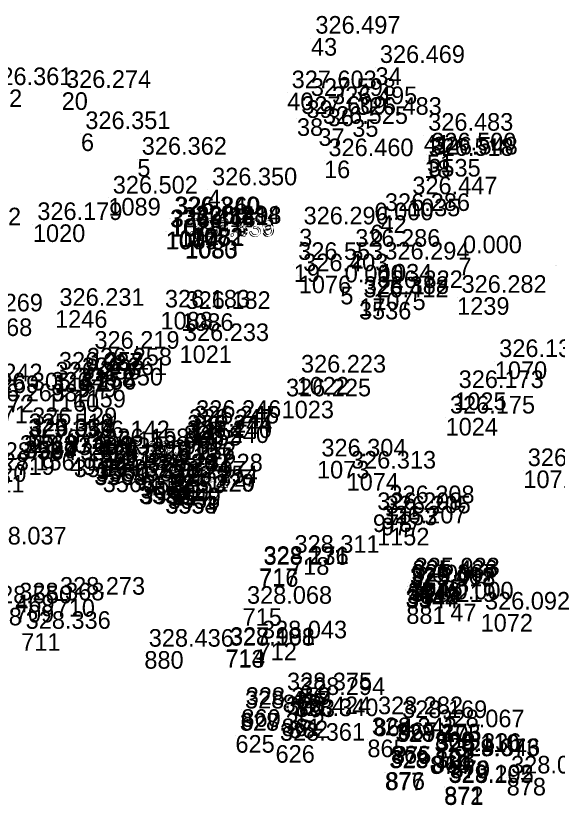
# Model space of a CAD drawing. Extents: x -829398 to -819400, y -1074439 to -1067977.
# Drawn here: x -823610.7 to -823573.8, y -1070251.6 to -1070197.8 of the extents above; entities that cross this region are included whole.
import ezdxf

# ---------------------------------------------------------------- set-up
doc = ezdxf.new("R2010")
doc.units = 0
doc.layers.add('Vrstva 60', color=7, linetype='Continuous')
doc.layers.add('Vrstva 61', color=7, linetype='Continuous')

msp = doc.modelspace()

# ---------------------------------------------------------------- linework, layer by layer
at = {"layer": 'Vrstva 60'}
for p, q in [((-823590.598, -1070199.294), (-823590.598, -1070199.294)), ((-823586.202, -1070201.291), (-823586.202, -1070201.291)), ((-823607.598, -1070202.992), (-823607.598, -1070202.992)), ((-823592.216, -1070203.012), (-823592.216, -1070203.012)), ((-823590.908, -1070203.54), (-823590.908, -1070203.54)), ((-823589.458, -1070204.102), (-823589.458, -1070204.102)), ((-823591.554, -1070204.765), (-823591.554, -1070204.765)), ((-823587.783, -1070204.827), (-823587.783, -1070204.827)), ((-823590.087, -1070205.446), (-823590.087, -1070205.446)), ((-823606.283, -1070205.799), (-823606.283, -1070205.799)), ((-823582.907, -1070205.912), (-823582.907, -1070205.912)), ((-823602.436, -1070207.547), (-823602.436, -1070207.547)), ((-823589.708, -1070207.648), (-823589.708, -1070207.648)), ((-823582.876, -1070207.626), (-823582.876, -1070207.626)), ((-823582.698, -1070207.252), (-823582.698, -1070207.252)), ((-823582.599, -1070207.539), (-823582.599, -1070207.539)), ((-823597.639, -1070209.635), (-823597.639, -1070209.635)), ((-823604.412, -1070210.197), (-823604.412, -1070210.197)), ((-823583.988, -1070210.246), (-823583.988, -1070210.246)), ((-823585.859, -1070211.384), (-823585.859, -1070211.384)), ((-823600.214, -1070211.606), (-823600.214, -1070211.606)), ((-823600.144, -1070211.632), (-823600.144, -1070211.632)), ((-823609.557, -1070212), (-823609.557, -1070212)), ((-823600.512, -1070212.501), (-823600.512, -1070212.501)), ((-823600.46, -1070212.486), (-823600.46, -1070212.486)), ((-823599.6, -1070212.333), (-823599.6, -1070212.333)), ((-823598.784, -1070212.226), (-823598.784, -1070212.226)), ((-823598.711, -1070212.264), (-823598.711, -1070212.264)), ((-823591.403, -1070212.298), (-823591.403, -1070212.298)), ((-823586.564, -1070212.02), (-823586.564, -1070212.02)), ((-823599.192, -1070213.133), (-823599.192, -1070213.133)), ((-823599.153, -1070213.092), (-823599.153, -1070213.092)), ((-823587.88, -1070213.824), (-823587.88, -1070213.824)), ((-823580.535, -1070214.267), (-823580.535, -1070214.267)), ((-823591.772, -1070214.721), (-823591.772, -1070214.721)), ((-823585.895, -1070214.697), (-823585.895, -1070214.697)), ((-823573.926, -1070214.791), (-823573.926, -1070214.791)), ((-823573.863, -1070214.779), (-823573.863, -1070214.779)), ((-823591.431, -1070215.494), (-823591.431, -1070215.494)), ((-823588.595, -1070216.253), (-823588.595, -1070216.253)), ((-823586.352, -1070216.64), (-823586.352, -1070216.64)), ((-823587.327, -1070217.278), (-823587.327, -1070217.278)), ((-823587.295, -1070217.043), (-823587.295, -1070217.043)), ((-823580.634, -1070216.965), (-823580.634, -1070216.965)), ((-823608.048, -1070217.853), (-823608.048, -1070217.853)), ((-823600.857, -1070217.967), (-823600.857, -1070217.967)), ((-823599.448, -1070218.063), (-823599.448, -1070218.063)), ((-823599.56, -1070220.253), (-823599.56, -1070220.253)), ((-823605.662, -1070220.777), (-823605.662, -1070220.777)), ((-823578.066, -1070221.343), (-823578.066, -1070221.343)), ((-823608.083, -1070222.205), (-823608.083, -1070222.205)), ((-823606.176, -1070221.92), (-823606.176, -1070221.92)), ((-823606.515, -1070222.577), (-823606.515, -1070222.577)), ((-823591.58, -1070222.404), (-823591.58, -1070222.404)), ((-823608.312, -1070222.876), (-823608.312, -1070222.876)), ((-823606.787, -1070223.284), (-823606.787, -1070223.284)), ((-823608.615, -1070223.568), (-823608.615, -1070223.568)), ((-823580.831, -1070223.457), (-823580.831, -1070223.457)), ((-823592.601, -1070224.025), (-823592.601, -1070224.025)), ((-823581.421, -1070225.196), (-823581.421, -1070225.196)), ((-823598.871, -1070225.877), (-823598.871, -1070225.877)), ((-823598.728, -1070225.493), (-823598.728, -1070225.493)), ((-823610.137, -1070226.4), (-823610.137, -1070226.4)), ((-823609.912, -1070225.983), (-823609.912, -1070225.983)), ((-823599.333, -1070226.498), (-823599.333, -1070226.498)), ((-823599.212, -1070226.092), (-823599.212, -1070226.092)), ((-823610.178, -1070226.77), (-823610.178, -1070226.77)), ((-823610.106, -1070226.739), (-823610.106, -1070226.739)), ((-823606.326, -1070226.884), (-823606.326, -1070226.884)), ((-823599.358, -1070226.867), (-823599.358, -1070226.867)), ((-823604.997, -1070227.424), (-823604.997, -1070227.424)), ((-823599.559, -1070227.205), (-823599.559, -1070227.205)), ((-823573.818, -1070227.288), (-823573.818, -1070227.288)), ((-823607.04, -1070227.894), (-823607.04, -1070227.894)), ((-823606.768, -1070228.03), (-823606.768, -1070228.03)), ((-823605.85, -1070227.601), (-823605.85, -1070227.601)), ((-823590.188, -1070228.125), (-823590.188, -1070228.125)), ((-823605.373, -1070228.542), (-823605.373, -1070228.542)), ((-823605.364, -1070228.58), (-823605.364, -1070228.58)), ((-823605.267, -1070228.34), (-823605.267, -1070228.34)), ((-823605.209, -1070228.17), (-823605.209, -1070228.17)), ((-823601.811, -1070228.316), (-823601.811, -1070228.316)), ((-823604.798, -1070229.057), (-823604.798, -1070229.057)), ((-823602.039, -1070229.133), (-823602.039, -1070229.133)), ((-823599.985, -1070229.138), (-823599.985, -1070229.138)), ((-823588.169, -1070228.952), (-823588.169, -1070228.952)), ((-823576.118, -1070228.78), (-823576.118, -1070228.78)), ((-823602.222, -1070229.491), (-823602.222, -1070229.491)), ((-823601.138, -1070229.626), (-823601.138, -1070229.626)), ((-823602.336, -1070229.84), (-823602.336, -1070229.84)), ((-823602.24, -1070229.885), (-823602.24, -1070229.885)), ((-823600.364, -1070230.195), (-823600.364, -1070230.195)), ((-823600.323, -1070229.946), (-823600.323, -1070229.946)), ((-823600.54, -1070230.517), (-823600.54, -1070230.517)), ((-823600.519, -1070230.524), (-823600.519, -1070230.524)), ((-823585.55, -1070231.31), (-823585.55, -1070231.31)), ((-823586.379, -1070231.776), (-823586.379, -1070231.776)), ((-823585.803, -1070232.003), (-823585.803, -1070232.003)), ((-823586.094, -1070232.691), (-823586.094, -1070232.691)), ((-823592.021, -1070234.692), (-823592.021, -1070234.692)), ((-823594.132, -1070235.51), (-823594.132, -1070235.51)), ((-823594.131, -1070235.449), (-823594.131, -1070235.449)), ((-823584.049, -1070236.669), (-823584.049, -1070236.669)), ((-823584, -1070236.707), (-823584, -1070236.707)), ((-823583.971, -1070236.399), (-823583.971, -1070236.399)), ((-823583.829, -1070236.235), (-823583.829, -1070236.235)), ((-823584.155, -1070236.872), (-823584.155, -1070236.872)), ((-823584.126, -1070236.979), (-823584.126, -1070236.979)), ((-823608.009, -1070237.55), (-823608.009, -1070237.55)), ((-823595.26, -1070238.17), (-823595.26, -1070238.17)), ((-823584.098, -1070238.039), (-823584.098, -1070238.039)), ((-823581.1, -1070237.871), (-823581.1, -1070237.871)), ((-823579.034, -1070238.565), (-823579.034, -1070238.565)), ((-823610.352, -1070239.878), (-823610.352, -1070239.878)), ((-823596.435, -1070241.025), (-823596.435, -1070241.025)), ((-823596.417, -1070240.971), (-823596.417, -1070240.971)), ((-823594.238, -1070240.527), (-823594.238, -1070240.527)), ((-823601.959, -1070241.097), (-823601.959, -1070241.097)), ((-823592.532, -1070244.07), (-823592.532, -1070244.07)), ((-823591.643, -1070244.389), (-823591.643, -1070244.389)), ((-823595.402, -1070245.31), (-823595.402, -1070245.31)), ((-823595.345, -1070245.061), (-823595.345, -1070245.061)), ((-823592.601, -1070245.696), (-823592.601, -1070245.696)), ((-823592.106, -1070245.834), (-823592.106, -1070245.834)), ((-823586.33, -1070245.7), (-823586.33, -1070245.7)), ((-823584.684, -1070245.96), (-823584.684, -1070245.96)), ((-823595.748, -1070246.824), (-823595.748, -1070246.824)), ((-823582.138, -1070246.589), (-823582.138, -1070246.589)), ((-823593.015, -1070247.51), (-823593.015, -1070247.51)), ((-823586.751, -1070247.131), (-823586.751, -1070247.131)), ((-823585.14, -1070247.555), (-823585.14, -1070247.555)), ((-823585.077, -1070247.589), (-823585.077, -1070247.589)), ((-823582.484, -1070248.273), (-823582.484, -1070248.273)), ((-823582.358, -1070248.203), (-823582.358, -1070248.203)), ((-823581.13, -1070248.57), (-823581.13, -1070248.57)), ((-823581.079, -1070248.552), (-823581.079, -1070248.552)), ((-823585.559, -1070249.383), (-823585.559, -1070249.383)), ((-823585.505, -1070249.351), (-823585.505, -1070249.351)), ((-823577.254, -1070249.74), (-823577.254, -1070249.74)), ((-823581.522, -1070250.339), (-823581.522, -1070250.339)), ((-823581.509, -1070250.389), (-823581.509, -1070250.389))]:
    msp.add_line(p, q, dxfattribs=at)

# ---------------------------------------------------------------- texts
for s, p in [('43', (-823590.598, -1070200.494)), ('34', (-823586.202, -1070202.491)), ('672', (-823612.966, -1070204.001)), ('20', (-823607.598, -1070204.192)), ('40', (-823592.216, -1070204.212)), ('39', (-823590.908, -1070204.74)), ('36', (-823589.458, -1070205.302)), ('38', (-823591.554, -1070205.965)), ('35', (-823587.783, -1070206.027)), ('37', (-823590.087, -1070206.646)), ('6', (-823606.283, -1070206.999)), ('41', (-823582.907, -1070207.112)), ('5', (-823602.436, -1070208.747)), ('16', (-823589.708, -1070208.848)), ('18', (-823582.876, -1070208.826)), ('51', (-823582.698, -1070208.452)), ('3535', (-823582.599, -1070208.739)), ('4', (-823597.639, -1070210.835)), ('1089', (-823604.412, -1070211.397)), ('1035', (-823583.988, -1070211.446)), ('42', (-823585.859, -1070212.584)), ('1020', (-823609.557, -1070213.2)), ('1078', (-823600.214, -1070212.806)), ('1085', (-823600.144, -1070212.832)), ('1079', (-823600.512, -1070213.701)), ('1084', (-823600.46, -1070213.686)), ('1077', (-823599.6, -1070213.533)), ('1082', (-823598.784, -1070213.426)), ('1081', (-823598.711, -1070213.464)), ('3', (-823591.403, -1070213.498)), ('6', (-823586.564, -1070213.22)), ('1080', (-823599.192, -1070214.333)), ('1083', (-823599.153, -1070214.292)), ('2', (-823587.88, -1070215.024)), ('7', (-823580.535, -1070215.467)), ('19', (-823591.772, -1070215.921)), ('1034', (-823585.895, -1070215.897)), ('1076', (-823591.431, -1070216.694)), ('5', (-823588.595, -1070217.453)), ('1075', (-823586.352, -1070217.84)), ('3536', (-823587.327, -1070218.478)), ('17', (-823587.295, -1070218.243)), ('1239', (-823580.634, -1070218.165)), ('1246', (-823608.048, -1070219.053)), ('1088', (-823600.857, -1070219.167)), ('1086', (-823599.448, -1070219.263)), ('1021', (-823599.56, -1070221.453)), ('1087', (-823605.662, -1070221.977)), ('1070', (-823578.066, -1070222.543)), ('1161', (-823608.083, -1070223.405)), ('1158', (-823606.176, -1070223.12)), ('979', (-823606.515, -1070223.777)), ('1022', (-823591.58, -1070223.604)), ('982', (-823608.312, -1070224.076)), ('1159', (-823606.787, -1070224.484)), ('3572', (-823613.056, -1070224.816)), ('1160', (-823608.615, -1070224.768)), ('1025', (-823580.831, -1070224.657)), ('3571', (-823613.474, -1070225.562)), ('1023', (-823592.601, -1070225.225)), ('1024', (-823581.421, -1070226.396)), ('3570', (-823609.912, -1070227.183)), ('1155', (-823598.871, -1070227.077)), ('1154', (-823598.728, -1070226.693)), ('3568', (-823610.137, -1070227.6)), ('981', (-823599.333, -1070227.698)), ('980', (-823599.212, -1070227.292)), ('3567', (-823610.178, -1070227.97)), ('3569', (-823610.106, -1070227.939)), ('3562', (-823606.326, -1070228.084)), ('1156', (-823599.358, -1070228.067)), ('1091', (-823605.85, -1070228.801)), ('3561', (-823604.997, -1070228.624)), ('1157', (-823599.559, -1070228.405)), ('719', (-823610.744, -1070229.079)), ('49', (-823607.04, -1070229.094)), ('3563', (-823606.768, -1070229.23)), ('1073', (-823590.188, -1070229.325)), ('720', (-823612.675, -1070229.56)), ('3564', (-823605.373, -1070229.742)), ('3565', (-823605.364, -1070229.78)), ('3559', (-823605.267, -1070229.54)), ('3560', (-823605.209, -1070229.37)), ('3551', (-823601.811, -1070229.516)), ('721', (-823612.809, -1070230.278)), ('3566', (-823604.798, -1070230.257)), ('3558', (-823602.039, -1070230.333)), ('3550', (-823599.985, -1070230.338)), ('1074', (-823588.169, -1070230.152)), ('1071', (-823576.118, -1070229.98)), ('3557', (-823602.222, -1070230.691)), ('1090', (-823601.138, -1070230.826)), ('3556', (-823602.336, -1070231.04)), ('3552', (-823602.24, -1070231.085)), ('3555', (-823600.364, -1070231.395)), ('3549', (-823600.323, -1070231.146)), ('3553', (-823600.54, -1070231.717)), ('3554', (-823600.519, -1070231.724)), ('1153', (-823585.55, -1070232.51)), ('978', (-823586.379, -1070232.976)), ('977', (-823585.803, -1070233.203)), ('1152', (-823586.094, -1070233.891)), ('718', (-823592.021, -1070235.892)), ('716', (-823594.132, -1070236.71)), ('717', (-823594.131, -1070236.649)), ('3548', (-823584.049, -1070237.869)), ('48', (-823584, -1070237.907)), ('3546', (-823583.971, -1070237.599)), ('3545', (-823583.829, -1070237.435)), ('3547', (-823584.155, -1070238.072)), ('3544', (-823584.126, -1070238.179)), ('710', (-823608.009, -1070238.75)), ('708', (-823612.988, -1070239.343)), ('709', (-823610.788, -1070239.138)), ('715', (-823595.26, -1070239.37)), ('881', (-823584.098, -1070239.239)), ('47', (-823581.1, -1070239.071)), ('1072', (-823579.034, -1070239.765)), ('711', (-823610.352, -1070241.078)), ('712', (-823594.238, -1070241.727)), ('713', (-823596.435, -1070242.225)), ('714', (-823596.417, -1070242.171)), ('880', (-823601.959, -1070242.297)), ('879', (-823592.532, -1070245.27)), ('863', (-823591.643, -1070245.589)), ('627', (-823595.402, -1070246.51)), ('860', (-823595.345, -1070246.261)), ('861', (-823592.601, -1070246.896)), ('862', (-823592.106, -1070247.034)), ('864', (-823586.33, -1070246.9)), ('867', (-823584.684, -1070247.16)), ('625', (-823595.748, -1070248.024)), ('868', (-823582.138, -1070247.789)), ('626', (-823593.015, -1070248.71)), ('865', (-823586.751, -1070248.331)), ('866', (-823585.14, -1070248.755)), ('875', (-823585.077, -1070248.789)), ('874', (-823582.484, -1070249.473)), ('869', (-823582.358, -1070249.403)), ('873', (-823581.13, -1070249.77)), ('870', (-823581.079, -1070249.752)), ('877', (-823585.559, -1070250.583)), ('876', (-823585.505, -1070250.551)), ('878', (-823577.254, -1070250.94)), ('872', (-823581.522, -1070251.539)), ('871', (-823581.509, -1070251.589))]:
    msp.add_text(s, height=1.2, dxfattribs=at).set_placement(p)
at = {"layer": 'Vrstva 61'}
for s, p in [('326.497', (-823590.298, -1070198.994)), ('326.469', (-823585.902, -1070200.991)), ('326.361', (-823612.666, -1070202.501)), ('326.274', (-823607.298, -1070202.692)), ('327.603', (-823591.916, -1070202.712)), ('327.598', (-823590.608, -1070203.24)), ('326.495', (-823589.158, -1070203.802)), ('327.609', (-823591.254, -1070204.465)), ('326.483', (-823587.483, -1070204.527)), ('326.351', (-823605.983, -1070205.499)), ('326.525', (-823589.787, -1070205.146)), ('326.483', (-823582.607, -1070205.612)), ('326.362', (-823602.136, -1070207.247)), ('326.500', (-823582.398, -1070206.952)), ('326.548', (-823582.299, -1070207.239)), ('326.460', (-823589.408, -1070207.348)), ('326.518', (-823582.576, -1070207.326)), ('326.350', (-823597.339, -1070209.335)), ('326.502', (-823604.112, -1070209.897)), ('326.447', (-823583.688, -1070209.946)), ('326.340', (-823599.914, -1070211.306)), ('326.860', (-823599.844, -1070211.332)), ('326.286', (-823585.559, -1070211.084)), ('326.382', (-823616.163, -1070212.064)), ('326.179', (-823609.257, -1070211.7)), ('326.821', (-823599.3, -1070212.033)), ('326.884', (-823598.484, -1070211.926)), ('326.498', (-823598.411, -1070211.964)), ('326.296', (-823591.103, -1070211.998)), ('0.000', (-823586.264, -1070211.72)), ('326.444', (-823600.212, -1070212.201)), ('326.815', (-823600.16, -1070212.186)), ('326.439', (-823598.892, -1070212.833)), ('326.836', (-823598.853, -1070212.792)), ('326.286', (-823587.58, -1070213.524)), ('0.000', (-823580.235, -1070213.967)), ('326.553', (-823591.472, -1070214.421)), ('326.294', (-823585.595, -1070214.397)), ('326.403', (-823591.131, -1070215.194)), ('0.000', (-823588.295, -1070215.953)), ('326.322', (-823586.052, -1070216.34)), ('326.388', (-823586.995, -1070216.743)), ('326.282', (-823580.334, -1070216.665)), ('326.412', (-823587.027, -1070216.978)), ('326.269', (-823614.676, -1070217.932)), ('326.231', (-823607.748, -1070217.553)), ('326.183', (-823600.557, -1070217.667)), ('326.182', (-823599.148, -1070217.763)), ('326.268', (-823615.404, -1070219.611)), ('326.233', (-823599.26, -1070219.953)), ('326.219', (-823605.362, -1070220.477)), ('326.137', (-823577.766, -1070221.043)), ('326.258', (-823605.876, -1070221.62)), ('326.258', (-823607.783, -1070221.905)), ('326.261', (-823606.215, -1070222.277)), ('326.223', (-823591.28, -1070222.104)), ('326.242', (-823614.701, -1070222.7)), ('326.256', (-823608.012, -1070222.576)), ('326.305', (-823612.756, -1070223.316)), ('326.256', (-823608.315, -1070223.268)), ('326.250', (-823606.487, -1070222.984)), ('326.173', (-823580.531, -1070223.157)), ('326.269', (-823614.933, -1070223.499)), ('326.225', (-823592.301, -1070223.725)), ('326.263', (-823613.174, -1070224.062)), ('326.175', (-823581.121, -1070224.896)), ('326.245', (-823598.571, -1070225.577)), ('326.246', (-823598.428, -1070225.193)), ('325.519', (-823609.837, -1070226.1)), ('326.129', (-823609.612, -1070225.683)), ('326.247', (-823598.912, -1070225.792)), ('325.356', (-823609.878, -1070226.47)), ('326.034', (-823609.806, -1070226.439)), ('326.142', (-823606.026, -1070226.584)), ('326.240', (-823599.058, -1070226.567)), ('326.244', (-823599.033, -1070226.198)), ('326.158', (-823604.697, -1070227.124)), ('326.240', (-823599.259, -1070226.905)), ('328.374', (-823610.444, -1070227.579)), ('0.000', (-823606.74, -1070227.594)), ('326.032', (-823606.468, -1070227.73)), ('326.159', (-823605.55, -1070227.301)), ('328.384', (-823612.375, -1070228.06)), ('326.019', (-823605.073, -1070228.242)), ('325.387', (-823604.967, -1070228.04)), ('326.113', (-823604.909, -1070227.87)), ('326.222', (-823601.511, -1070228.016)), ('326.304', (-823589.888, -1070227.825)), ('328.156', (-823612.509, -1070228.778)), ('325.300', (-823605.064, -1070228.28)), ('325.298', (-823604.498, -1070228.757)), ('326.313', (-823587.869, -1070228.652)), ('326.067', (-823575.818, -1070228.48)), ('325.374', (-823601.922, -1070229.191)), ('326.217', (-823601.739, -1070228.833)), ('326.297', (-823600.838, -1070229.326)), ('326.228', (-823599.685, -1070228.838)), ('325.327', (-823602.036, -1070229.54)), ('326.255', (-823601.94, -1070229.585)), ('326.254', (-823600.023, -1070229.646)), ('326.229', (-823600.24, -1070230.217)), ('325.420', (-823600.219, -1070230.224)), ('325.527', (-823600.064, -1070229.895)), ('326.208', (-823586.079, -1070231.476)), ('326.208', (-823585.25, -1070231.01)), ('326.205', (-823585.503, -1070231.703)), ('326.207', (-823585.794, -1070232.391)), ('328.037', (-823613.058, -1070233.828)), ('328.311', (-823591.721, -1070234.392)), ('328.136', (-823593.832, -1070235.21)), ('328.271', (-823593.831, -1070235.149)), ('325.436', (-823583.671, -1070236.099)), ('325.923', (-823583.529, -1070235.935)), ('325.402', (-823583.855, -1070236.572)), ('325.918', (-823583.826, -1070236.679)), ('325.367', (-823583.749, -1070236.369)), ('0.000', (-823583.7, -1070236.407)), ('328.273', (-823607.709, -1070237.25)), ('328.550', (-823612.688, -1070237.843)), ('328.368', (-823610.488, -1070237.638)), ('328.068', (-823594.96, -1070237.87)), ('328.219', (-823583.798, -1070237.739)), ('0.000', (-823580.8, -1070237.571)), ('328.469', (-823613.885, -1070238.443)), ('326.092', (-823578.734, -1070238.265)), ('328.336', (-823610.052, -1070239.578)), ('328.043', (-823593.938, -1070240.227)), ('328.436', (-823601.659, -1070240.797)), ('328.108', (-823596.135, -1070240.725)), ('327.981', (-823596.117, -1070240.671)), ('328.375', (-823592.232, -1070243.77)), ('328.294', (-823591.343, -1070244.089)), ('328.359', (-823595.045, -1070244.761)), ('328.417', (-823595.102, -1070245.01)), ('328.424', (-823592.301, -1070245.396)), ('328.282', (-823586.03, -1070245.4)), ('328.340', (-823591.806, -1070245.534)), ('328.169', (-823584.384, -1070245.66)), ('328.352', (-823595.448, -1070246.524)), ('328.067', (-823581.838, -1070246.289)), ('328.342', (-823586.451, -1070246.831)), ('328.361', (-823592.715, -1070247.21)), ('328.373', (-823584.84, -1070247.255)), ('329.105', (-823584.777, -1070247.289)), ('329.110', (-823582.184, -1070247.973)), ('328.336', (-823582.058, -1070247.903)), ('329.073', (-823580.83, -1070248.27)), ('328.346', (-823580.779, -1070248.252)), ('328.391', (-823585.259, -1070249.083)), ('329.108', (-823585.205, -1070249.051)), ('328.075', (-823576.954, -1070249.44)), ('329.102', (-823581.222, -1070250.039)), ('328.295', (-823581.209, -1070250.089))]:
    msp.add_text(s, height=1.2, dxfattribs=at).set_placement(p)

doc.saveas('drawing.dxf')
